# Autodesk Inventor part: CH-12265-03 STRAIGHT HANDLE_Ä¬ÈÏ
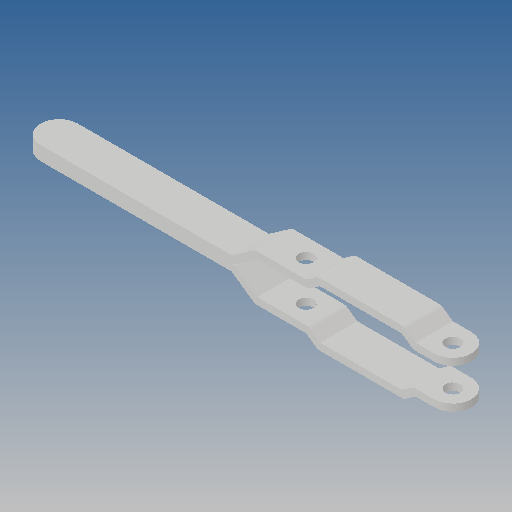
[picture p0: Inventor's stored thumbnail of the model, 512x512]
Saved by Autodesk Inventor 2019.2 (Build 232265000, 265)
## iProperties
Created: 2012-09
Part Number: CH-12265-03 STRAIGHT HANDLE_Ä¬ÈÏ
Material: Ogólny
Document SubType Name: Modeling
Designer: CADENGINEERING4
Density: 1 g/cm^3
Appearance: Domyślna
Author: CADENGINEERING4
Revision Number: ÈÎºÎ
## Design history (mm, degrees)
feature "NONE" [ÊäÈë]
feature "ÊäÈë2"
node "Bryła1"
node "Bryła2"
